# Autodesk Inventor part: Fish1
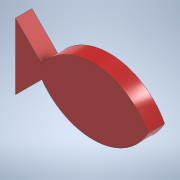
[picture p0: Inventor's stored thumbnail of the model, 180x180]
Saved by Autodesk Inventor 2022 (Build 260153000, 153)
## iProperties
Created: 2021-07
Part Number: Fish1
Material: Generic
Document SubType Name: Modeling
Designer: bluer
Density: 1 g/cm^3
Appearance: Default
Author: bluer
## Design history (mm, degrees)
sketch "Sketch1"
  geometry: L1 (0, 0)-(50.8, 0); L2 (50.8, 0)-(50.8, 25.4); L3 (50.8, 25.4)-(0, 25.4); L4 (0, 25.4)-(0, 0); L5 (10.16, 15.24)-(0, 25.4); L6 (0, 0)-(10.16, 10.16); A1 r 23.874 centre (29.702, 1.526) between (50.8, 12.7) and (10.16, 15.24); A2 r 23.874 centre (29.702, 23.874) between (10.16, 10.16) and (50.8, 12.7)
  constraints: 12 end point, 4 point on circle, 2 centre point, 2 parallel, 2 tangent, 1 horizontal, 1 midpoint, 1 perpendicular
  dimensions: "d0" = 50.8 distance of L2.end L3.end; "d1" = 25.4 distance of L1.end L2.end; "d5" = 23.87424 radius of A1 (derived); "d6" = 10.16 horizontal distance of L1.start L6.end; "d7" = 10.16 horizontal distance of L1.start L6.end; "d11" = 12.7 vertical distance of L1.start A1.start (derived); "d12" = 29.70224 horizontal distance of A1.centre L1.start
extrude "Extrusion1" new body sketch "Sketch1" distance "d8" = 6.35; taper "d9" = 0 deg
body "Solid1"
